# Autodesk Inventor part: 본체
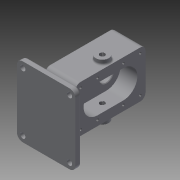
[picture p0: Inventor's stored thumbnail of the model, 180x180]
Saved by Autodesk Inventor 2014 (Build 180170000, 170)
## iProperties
Created: 2020-04
Part Number: 본체
Material: Generic
Document SubType Name: Modeling
Designer: kh
Density: 1 g/cm^3
Appearance: Default
Author: kh
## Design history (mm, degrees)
sketch "스케치1"
  geometry: L1 (-50, -60)-(50, -60); L2 (50, -60)-(50, 60); L3 (50, 60)-(-50, 60); L4 (-50, 60)-(-50, -60); L5 (-50, -60)-(50, 60); L6 (50, -60)-(-50, 60); 1 further point
  constraints: 12 end point, 2 midpoint, 2 parallel, 1 horizontal, 1 perpendicular
  dimensions: "d0" = 100 distance of L3.end L2.end; "d1" = 120 distance of L2.end L1.end
extrude "돌출1" new body sketch "스케치1" distance "d2" = 10; taper "d3" = 0 deg
fillet "모깎기1" dims "d4" = 10
hole "구멍1" diameter "d7" = 9; stored, may be unused: countersink angle "d11" = 90 deg, drill point angle "d13" = 118 deg; dims "d5" = 10, "d6" = 10, "d8" = 6, "d9" = 4, "d10" = 2, "d12" = 8
node "작업 평면1"
sketch "스케치2"
  geometry: L1 (-40, -60)-(40, -60) reference; L2 (50, -50)-(50, 50) reference; L3 (40, 60)-(-40, 60) reference; L4 (-50, 50)-(-50, -50) reference; L5 (-33, 40)-(20, 40); L6 (20, 40)-(20, -40); L7 (20, -40)-(-33, -40); L8 (-33, -40)-(-33, 40); C1 r 4.5 at (-40, -50) reference; C2 r 4.5 at (40, -50) reference; C3 r 4.5 at (-40, 50) reference; C4 r 4.5 at (40, 50) reference; A1 r 10 centre (-40, -50) between (-50, -50) and (-40, -60) reference; A2 r 10 centre (40, -50) between (40, -60) and (50, -50) reference; A3 r 10 centre (40, 50) between (50, 50) and (40, 60) reference; A4 r 10 centre (-40, 50) between (-40, 60) and (-50, 50) reference; 2 further points
  constraints: 8 end point, 2 parallel, 1 horizontal, 1 horizontal alignment, 1 midpoint, 1 perpendicular
  dimensions: "d15" = 70 distance between parallel lines of L6 L4; "d16" = 17 distance between parallel lines of L8 L4; "d17" = 80 distance of L5.end L6.end
extrude "돌출2" join sketch "스케치2" distance "d18" = 120; taper "d19" = 0 deg
sketch "스케치3"
  geometry: L1 (80, 0)-(0, 0) reference; L2 (0, 0)-(0, -120) reference; L3 (80, -120)-(0, -120) reference; L4 (80, 0)-(80, -120) reference; L5 (40, -38)-(40, -82); L6 (16, -38)-(16, -82); L7 (64, -82)-(64, -38); A1 r 24 centre (40, -38) between (64, -38) and (16, -38); A2 r 24 centre (40, -82) between (16, -82) and (64, -82); 3 further points
  constraints: 8 end point, 4 point on circle, 4 tangent, 2 centre point, 2 midpoint, 2 parallel, 1 vertical alignment
  dimensions: "d20" = 48 diameter of A2; "d21" = 44 distance of L5.start L5.end; "d22" = 60 distance from line of point (40, -60) L1
extrude "돌출3" cut sketch "스케치3" distance "d23" = 29; taper "d24" = 0 deg
sketch "스케치4"
  geometry: L1 (16, -82)-(16, -38) reference; L2 (64, -38)-(64, -82) reference; C1 r 12.5 at (40, -38); C2 r 12.5 at (40, -82); A1 r 24 centre (40, -82) between (16, -82) and (64, -82) reference; A2 r 24 centre (40, -38) between (64, -38) and (16, -38) reference; 1 further point
  constraints: 2 centre point, 2 coincident
  dimensions: "d25" = 25 diameter of C1; "d26" = 25 diameter of C2
extrude "돌출4" cut sketch "스케치4" distance "d27" = 15; taper "d28" = 0 deg
sketch "스케치5"
  geometry: L1 (20, 150)-(-33, 150) reference; L2 (-33, 150)-(-33, 30) reference; L3 (20, 30)-(-33, 30) reference; L4 (20, 150)-(20, 30) reference; L5 (-24, 124.5)-(-24, 99.5) reference; L6 (-9, 124.5)-(-9, 99.5) reference; L7 (-33, 112)-(-50, 112); L8 (-33, 131)-(-50, 131); L9 (-50, 131)-(-50, 126.404); L10 (-50, 126.404)-(-49.3, 126); L11 (-49.3, 126)-(-42.7, 126); L12 (-42.7, 126)-(-42.7, 112); L13 (-42.7, 112)-(-33, 112); L14 (-33, 131)-(-33, 112); 2 further points
  constraints: 16 end point, 4 perpendicular, 3 point on line, 2 parallel, 1 collinear, 1 horizontal alignment, 1 midpoint
  dimensions: "d29" = 17 distance of L7.start L7.end; "d30" = 30 deg angle of L11 L10; "d31" = 38 diameter of L8 L7; "d32" = 28 diameter of L11 L7; "d33" = 7.3 horizontal distance of L9.end L11.end; "d34" = 0.7 horizontal distance of L9.end L10.end; "d35" = 17 distance of L8.start L8.end
revolve "회전1" sketch "스케치5" stored, may be unused: angle "d36" = 90 deg
sketch "스케치6"
  geometry: C1 r 14 at (0, 0) reference; C2 r 8.5 at (0, 0); 1 further point
  constraints: 1 centre point, 1 coincident
  dimensions: "d37" = 17 diameter of C2
extrude "돌출5" cut sketch "스케치6" stored distance "d38" = 7.3; taper "d39" = 0 deg
sketch "스케치7"
  geometry: L1 (-40, 0)-(-40, 10) reference; L2 (-40, 0)-(40, 0) reference; L3 (40, 10)-(40, 0) reference; L4 (-40, 10)-(40, 10) reference; L5 (20, 150)-(-33, 150) reference; L6 (-33, 150)-(-33, 30) reference; L7 (20, 30)-(-33, 30) reference; L8 (20, 150)-(20, 30) reference; L9 (-40, 10)-(-50, 10) reference; L10 (-50, 10)-(-50, 0) reference; L11 (-50, 0)-(-40, 0) reference; L12 (-40, 0)-(-40, 10) reference; L13 (20, 10)-(-33, 10); L14 (20, 10)-(8.453, 30); L15 (-33, 10)-(-21.453, 30); L16 (8.453, 30)-(-21.453, 30); 1 further point
  constraints: 8 end point, 2 point on line, 1 collinear, 1 horizontal alignment, 1 perpendicular
  dimensions: "d40" = 53 distance of L13.start L13.end; "d41" = 17 distance of L9.end L13.end; "d42" = 60 deg angle of L15 L13; "d43" = 60 deg angle of L13 L14
extrude "돌출6" join sketch "스케치7" stored distance "d44" = 48; taper "d45" = 0 deg
fillet "모깎기2" dims "d46" = 3
fillet "모깎기3" dims "d47" = 3
fillet "모깎기4" dims "d48" = 3
fillet "모깎기5" dims "d49" = 9
fillet "모깎기6" dims "d50" = 3
chamfer "모따기1" distance "d51" = 1; stored, may be unused: second distance "d52" = 2, angle "d53" = 30 deg
sketch "스케치8"
  geometry: L1 (36.787, -20.42)-(36.787, 20.42); L2 (36.787, 20.42)-(43.213, 20.42); L3 (43.213, 20.42)-(43.213, -20.42); L4 (43.213, -20.42)-(36.787, -20.42); L5 (36.787, -20.42)-(43.213, 20.42); L6 (36.787, 20.42)-(43.213, -20.42); L7 (50, -50)-(50, 50) reference; L8 (-40, -60)-(40, -60) reference; 2 further points
  constraints: 4 end point, 1 midpoint, 2 other
  dimensions: "d54" = 10 distance from line of L7 point (40, 0); "d55" = 60 distance from line of L8 point (40, 0)
feature "엠보싱1" sketch "스케치8" dims "d0" = 100, "d1" = 120, "d14" = 140, "d56" = 0.5, "d57" = 0
sketch "스케치10"
  geometry: L1 (0, 0)-(62, 0) reference; L2 (52, -120)-(10, -120) reference; L3 (71, -9)-(71, -111) reference; L4 (-9, -111)-(-9, -9) reference; A1 r 9 centre (0, -9) between (0, 0) and (-9, -9) reference; A2 r 9 centre (62, -9) between (71, -9) and (62, 0) reference; A3 r 9 centre (62, -111) between (62, -120) and (71, -111) reference; A4 r 9 centre (0, -111) between (-9, -111) and (0, -120) reference; 9 further points
  constraints: 4 coincident, 4 vertical alignment, 2 horizontal alignment
  dimensions: "d72" = 29 distance of point (62, -38) point (62, -9); "d73" = 44 distance of point (62, -38) point (62, -82)
hole "구멍3" sketch "스케치10" at (0, -9), (62, -9), (62, -111), (0, -111), (0, -38), (62, -38), (0, -82), (62, -82) diameter "d74" = 4.134; stored, may be unused: countersink angle "d78" = 90 deg, drill point angle "d80" = 118 deg; dims "d75" = 10, "d76" = 4, "d77" = 2, "d79" = 12
node "작업 평면2"
sketch "스케치11"
  geometry: L1 (-9, -111)-(-9, -9) reference; L2 (71, -9)-(71, -111) reference; L3 (81, -150)-(-19, -150) reference; L4 (0, 0)-(62, 0) reference; L5 (-17, -60)-(79, -60); L6 (-9, -49)-(-17, -49); L7 (-17, -49)-(-17, -60); L8 (-9, -60)-(-9, -49); L9 (-17, -60)-(-9, -60); 1 further point
  constraints: 10 end point, 2 collinear, 2 point on line, 1 midpoint, 1 parallel, 1 perpendicular
  dimensions: "d83" = 90 distance between parallel lines of L3 L5; "d84" = 8 distance from line of L5.end L2; "d85" = 8 distance from line of L1 L5.start; "d86" = 8 distance of L6.start L6.end; "d87" = 22 diameter of L6 L5
revolve "회전3" sketch "스케치11" stored, may be unused: angle "d88" = 90 deg
hole "구멍4" diameter "d91" = 8.376; stored, may be unused: countersink angle "d95" = 90 deg, drill point angle "d97" = 118 deg; dims "d89" = 10, "d90" = 10, "d92" = 96, "d93" = 4, "d94" = 2, "d96" = 8
fillet "모깎기8" dims "d98" = 3
fillet "모깎기9" dims "d99" = 0.5
fillet "모깎기10" dims "d100" = 3
node "솔리드1"
mirror "대칭1"
mirror "대칭2"
mirror "대칭4"
node "투영된 루프1"
node "투영된 루프2"
node "투영된 루프3"
node "투영된 루프4"
node "투영된 루프5"
node "투영된 루프6"
node "투영된 루프7"
node "투영된 루프8"
node "투영된 루프9"
other parameters: "d82" = -14
